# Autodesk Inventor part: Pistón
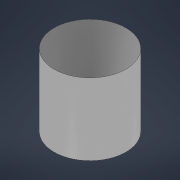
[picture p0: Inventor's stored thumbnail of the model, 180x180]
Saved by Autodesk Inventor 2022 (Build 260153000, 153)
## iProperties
Created: 2021-08
Part Number: Pistón
Material: Nickel-Copper Alloy 400
Document SubType Name: Modeling
Designer: user
Density: 8.83 g/cm^3
Appearance: Chrome - Polished
Mass: 1.18269 g
Surface Area: 5.0437 cm^2
Volume: 0.13394 cm^3
Author: user
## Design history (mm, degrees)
sketch "Sketch2"
  geometry: L1 (0, 4)-(8, 4); L2 (8, 4)-(8, -4); L3 (8, -4)-(0, -4); L4 (0, -4)-(0, 4); L5 (8, 0)-(7.5, 0); L6 (7.5, 0)-(7.5, -3.5); L7 (7.5, -3.5)-(0, -3.5); 2 further points
  constraints: 14 end point, 3 perpendicular, 2 horizontal, 2 midpoint, 2 parallel, 1 coincident, 1 horizontal alignment, 1 point on line
  dimensions: "d0" = 8 distance of L2.end L3.end; "d1" = 8 distance of L1.end L2.end; "d2" = 0.5 distance of L5.start L5.end; "d3" = 3.5 distance of L5.end L6.end
revolve "Revolution1" sketch "Sketch2" stored, may be unused: angle "d4" = 90 deg
sketch "Sketch3"
  geometry: L1 (-4, 0)-(4, 0) reference; C1 r 1 at (0, 1.5); 1 further point
  constraints: 1 centre point
  dimensions: "d5" = 2 diameter of C1; "d6" = 1.5 distance from line of L1 C1.centre
extrude "Extrusion1" join sketch "Sketch3" stored distance "d7" = 7.25; taper "d8" = 0 deg
sketch "Sketch4"
  geometry: C1 r 0.75 at (0, 1.5); 2 further points
  constraints: 1 centre point, 1 other
  dimensions: "d9" = 1.5 diameter of C1
extrude "Extrusion2" cut sketch "Sketch4" stored distance "d10" = 1; taper "d11" = 0 deg
body "Solid1"
